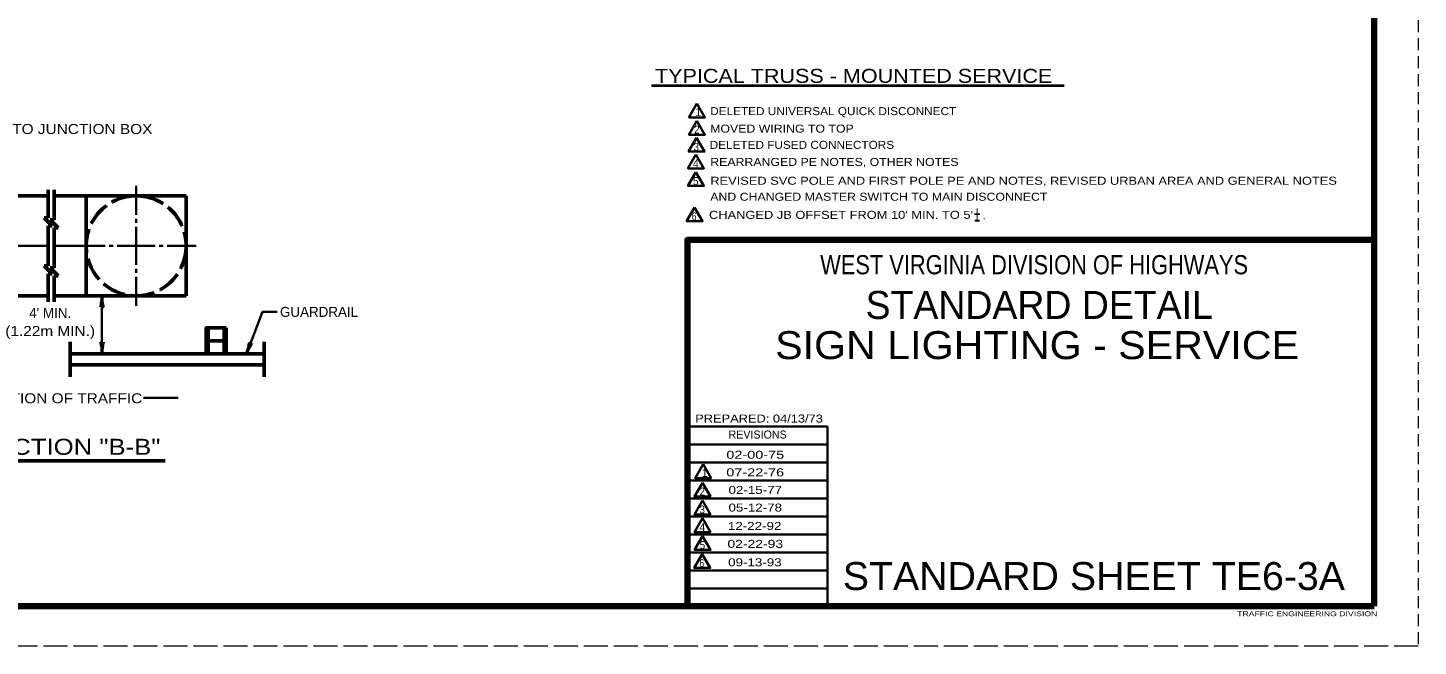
# Model space of a CAD drawing. Extents: x -68 to 612, y -58 to 382.
# Drawn here: x 265 to 612.4, y -57.9 to 96.7 of the extents above; entities that cross this region are included whole.
import ezdxf
from ezdxf.enums import TextEntityAlignment as Align

# ---------------------------------------------------------------- set-up
doc = ezdxf.new("R2010")
doc.units = 0
doc.linetypes.add('LONG_DASHED', pattern=[7.5, 6, -1.5])
doc.linetypes.add('MEDIUM_DASHED', pattern=[4.5, 3, -1.5])
doc.layers.add('1', color=7, linetype='Continuous', lineweight=53)
doc.layers.add('61', color=7, linetype='Continuous', lineweight=35)

msp = doc.modelspace()

# ---------------------------------------------------------------- linework, layer by layer
at = {"layer": '1', "linetype": 'MEDIUM_DASHED', "lineweight": 13}
msp.add_line((612.409, 382.166), (612.389, -57.854), dxfattribs=at)
at = {"layer": '1', "lineweight": 40}
msp.add_line((420.868, 82.321), (523.938, 82.321), dxfattribs=at)
at = {"layer": '1'}
for p, q in [((270.054, 56.23), (270.054, 49.23)), ((271.554, 56.23), (271.554, 48.73)), ((237.054, 54.73), (270.054, 54.73)), ((304.554, 54.73), (271.554, 54.73)), ((279.554, 54.73), (279.554, 29.729)), ((304.554, 54.73), (304.554, 29.729)), ((269.054, 49.23), (270.054, 49.23)), ((269.054, 49.23), (271.054, 47.23)), ((270.554, 48.73), (272.554, 46.73)), ((270.554, 48.73), (271.554, 48.73)), ((270.054, 47.23), (271.054, 47.23)), ((270.054, 47.23), (270.054, 37.23)), ((271.554, 46.73), (271.554, 36.73)), ((271.554, 46.73), (272.554, 46.73)), ((269.054, 37.23), (270.054, 37.23)), ((269.054, 37.23), (271.054, 35.23)), ((270.054, 35.23), (271.054, 35.23)), ((270.054, 35.23), (270.054, 28.229)), ((270.554, 36.73), (271.554, 36.73)), ((270.554, 36.73), (272.554, 34.73)), ((271.554, 34.73), (271.554, 28.229)), ((271.554, 34.73), (272.554, 34.73)), ((237.054, 29.729), (270.054, 29.729)), ((304.554, 29.729), (271.554, 29.729)), ((310.054, 15.229), (310.054, 21.729)), ((314.054, 15.229), (314.054, 21.729)), ((314.554, 15.229), (314.554, 21.729)), ((275.554, 18.229), (275.554, 9.479)), ((310.054, 18.479), (314.054, 18.479)), ((324.054, 18.229), (324.054, 9.479)), ((324.054, 15.229), (275.554, 15.229)), ((324.054, 12.479), (275.554, 12.479)), ((251.024, -11.547), (299.314, -11.547))]:
    msp.add_line(p, q, dxfattribs=at)
at = {"layer": '1', "lineweight": 35}
for p, q in [((292.054, 57.23), (292.054, 54.73)), ((292.054, 54.73), (292.054, 49.98)), ((292.054, 48.98), (292.054, 47.98)), ((292.054, 46.98), (292.054, 42.23)), ((262.054, 42.23), (270.054, 42.23)), ((279.554, 42.23), (271.554, 42.23)), ((284.304, 42.23), (279.554, 42.23)), ((286.304, 42.23), (285.304, 42.23)), ((292.054, 42.23), (287.304, 42.23)), ((298.804, 42.23), (297.804, 42.23)), ((304.554, 42.23), (299.804, 42.23)), ((307.054, 42.23), (304.554, 42.23)), ((292.054, 36.48), (292.054, 35.48)), ((292.054, 34.48), (292.054, 29.729)), ((283.513, 29.729), (283.513, 15.229)), ((292.054, 29.729), (292.054, 27.229)), ((293.893, 4.222), (302.534, 4.222)), ((464.789, -7.434), (429.809, -7.434)), ((464.789, -11.934), (429.809, -11.934)), ((464.789, -16.434), (429.809, -16.434)), ((464.789, -20.954), (429.809, -20.954)), ((464.789, -25.434), (429.809, -25.434)), ((464.789, -29.914), (429.809, -29.914)), ((464.789, -34.414), (429.809, -34.414)), ((464.789, -38.914), (429.809, -38.914)), ((464.789, -43.434), (429.809, -43.434))]:
    msp.add_line(p, q, dxfattribs=at)
for points in [[(432.175, 77.785), (430.175, 74.321), (434.175, 74.321)], [(432.175, 73.469), (430.175, 70.005), (434.175, 70.005)], [(432.078, 69.251), (430.078, 65.787), (434.078, 65.787)], [(431.914, 65.055), (429.914, 61.591), (433.914, 61.591)], [(431.914, 60.666), (429.914, 57.202), (433.914, 57.202)], [(431.606, 51.83), (429.606, 48.366), (433.606, 48.366)], [(433.699, -12.375), (431.699, -15.839), (435.699, -15.839)], [(433.539, -17.001), (431.539, -20.465), (435.539, -20.465)], [(433.539, -21.468), (431.539, -24.932), (435.539, -24.932)], [(433.539, -25.88), (431.539, -29.344), (435.539, -29.344)], [(433.594, -30.346), (431.594, -33.81), (435.594, -33.81)], [(433.51, -34.855), (431.51, -38.319), (435.51, -38.319)]]:
    msp.add_lwpolyline(points, close=True, dxfattribs=at)
for points in [[(296.804, 42.23), (292.054, 42.23), (292.054, 37.48)], [(319.597, 15.229), (323.64, 25.744), (327.259, 25.744)], [(464.789, -47.914), (464.789, -2.954), (429.809, -2.954)]]:
    msp.add_lwpolyline(points, dxfattribs=at)
at = {"layer": '1', "lineweight": 158}
msp.add_lwpolyline([(429.789, -47.874), (429.789, 43.706), (601.449, 43.706)], dxfattribs=at)
at = {"layer": '1'}
msp.add_lwpolyline([(309.554, 15.229), (309.554, 21.729), (314.554, 21.729)], dxfattribs=at)
at = {"layer": '1', "linetype": 'LONG_DASHED'}
msp.add_circle((292.054, 42.23), 12.5, dxfattribs=at)
at = {"layer": '1', "lineweight": 40}
for centre, major_axis, ratio, start_param, end_param in [((283.302, 28.609), (0.176, 1.756), 0.07063, 3.1407148, 5.41811), ((283.302, 28.609), (0.176, 1.756), 0.07063, 3.1407148, 5.41811), ((283.79, 28.638), (-0.156, 1.786), 0.122415, 0.8963533, 3.1415927), ((283.79, 28.638), (-0.156, 1.786), 0.122415, 0.8963533, 3.1415927), ((283.245, 16.33), (0.156, -1.786), 0.122415, 0.8963533, 3.1415927), ((283.733, 16.359), (-0.176, -1.756), 0.07063, 3.1407148, 5.41811), ((319.731, 16.347), (-0.495, -1.723), 0.122415, 0.8963533, 3.1415927), ((319.731, 16.347), (-0.495, -1.723), 0.122415, 0.8963533, 3.1415927), ((320.197, 16.199), (-0.794, -1.576), 0.07063, 3.1407148, 5.41811), ((320.197, 16.199), (-0.794, -1.576), 0.07063, 3.1407148, 5.41811)]:
    msp.add_ellipse(centre, major_axis=major_axis, ratio=ratio, start_param=start_param, end_param=end_param, dxfattribs=at)
at = {"layer": '61', "lineweight": 158}
for p, q in [((601.429, 372.166), (601.449, -47.874)), ((601.449, -47.874), (-37.611, -47.854))]:
    msp.add_line(p, q, dxfattribs=at)
at = {"layer": '61', "linetype": 'LONG_DASHED', "lineweight": 13}
msp.add_line((612.389, -57.854), (-67.671, -57.874), dxfattribs=at)

# ---------------------------------------------------------------- texts
at = {"layer": '1'}
for s, height, width, p in [('TYPICAL TRUSS - MOUNTED SERVICE', 3.5, 1.15, (421.704, 82.958)), ('DELETED UNIVERSAL QUICK DISCONNECT', 2, 1.1, (435.506, 74.894)), ('2', 2, 0.9, (431.494, 70.287)), ('MOVED WIRING TO TOP', 2, 1.15, (435.485, 70.52)), ('3', 2, 0.9, (431.346, 65.934)), ('DELETED FUSED CONNECTORS', 2, 1.1, (435.357, 66.465)), ('4', 2, 0.95, (431.206, 61.813)), ('REARRANGED PE NOTES, OTHER NOTES', 2, 1.15, (435.512, 62.189)), ('5', 2, 0.9, (431.206, 57.424)), ('REVISED SVC POLE AND FIRST POLE PE AND NOTES, REVISED URBAN AREA AND GENERAL NOTES', 2, 1.2, (435.513, 57.488)), ('AND CHANGED MASTER SWITCH TO MAIN DISCONNECT', 2, 1.15, (435.513, 53.488)), ('6', 2, 0.8, (430.898, 48.588)), ("CHANGED JB OFFSET FROM 10' MIN. TO 5'", 2, 1.2, (435.205, 48.964)), ('PREPARED: 04/13/73', 1.998, 1.2, (431.749, -1.954)), ('2', 2, 0.9, (432.862, -20.215)), ('3', 2, 0.9, (432.831, -24.71)), ('4', 2, 0.95, (432.831, -29.122)), ('5', 2, 0.9, (432.886, -33.588)), ('6', 2, 0.8, (432.802, -38.097)), ('STANDARD SHEET TE6-3A', 6.993, 1.05, (468.629, -43.834)), ('TRAFFIC ENGINEERING DIVISION', 1.2, 1.35, (567.169, -50.374))]:
    msp.add_text(s, height=height, dxfattribs=dict(at, width=width)).set_placement(p)
for s, height, p in [('1', 2, (431.752, 74.66)), ('REVISIONS', 1.998, (440.069, -5.954)), ('1', 2, (433.382, -15.535))]:
    msp.add_text(s, height=height, dxfattribs=at).set_placement(p)
for s, height, width, p in [('TO JUNCTION BOX', 2.5, 1.15, (278.601, 70.17)), ('+', 4, 0.55, (502.203, 48.217)), ('WEST VIRGINIA DIVISION OF HIGHWAYS', 4.795, 0.85, (516.437, 35.106)), ('(1.22m MIN.)', 2.5, 1.15, (270.569, 19.679)), ('SIGN LIGHTING - SERVICE', 6.993, 1.1, (517.18, 13.897)), ('DIRECTION OF TRAFFIC', 2.5, 1.15, (271.145, 2.852)), ('SECTION "B-B"', 4, 1.2, (275.325, -10.027)), ('02-00-75', 2, 1.35, (446.758, -11.014)), ('07-22-76', 2, 1.35, (446.738, -15.414)), ('02-15-77', 2, 1.25, (446.758, -19.814)), ('05-12-78', 2, 1.25, (446.758, -24.214)), ('12-22-92', 2, 1.25, (446.598, -28.814)), ('02-22-93', 2, 1.3, (446.758, -33.294)), ('09-13-93', 2, 1.25, (446.658, -37.894))]:
    msp.add_text(s, height=height, dxfattribs=dict(at, width=width)).set_placement(p, align=Align.CENTER)
for s, height, p in [('-', 4, (502.212, 46.962)), ('.', 2, (503.983, 48.824)), ('STANDARD DETAIL', 6.993, (517.706, 23.946)), ("4' MIN.", 2.5, (270.569, 24.179)), ('GUARDRAIL', 2.5, (337.754, 24.46))]:
    msp.add_text(s, height=height, dxfattribs=at).set_placement(p, align=Align.CENTER)

doc.saveas('drawing.dxf')
